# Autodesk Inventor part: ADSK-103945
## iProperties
Shininess: 0.0
Created: 2000-10
Part Number: ADSK-103945
Document SubType Name: Modeling
Designer: gao
Stock Number: ADSK-103945
Density: 1 g/cm^3
Density: 0.0
Volumn: 0.0
Area: 0.0
PropertySet Name: Model Information
Control State: 0
Master: False
Checked Out: False
Author: gao
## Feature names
1. Hole12
